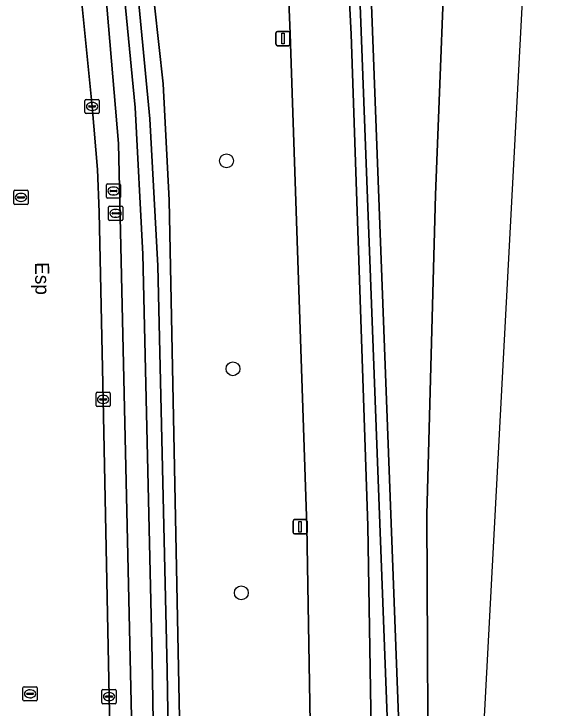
# Model space of a CAD drawing. Extents: x 161385 to 162589, y 388479 to 389756.
# Drawn here: x 162491.62 to 162530.48, y 389010.14 to 389059.08 of the extents above; entities that cross this region are included whole.
import ezdxf

# ---------------------------------------------------------------- set-up
doc = ezdxf.new("R2010")
doc.units = 0
for name, color, linetype in [('IMGEO_Berm_groen', 7, 'Continuous'), ('IMGEO_Boom', 7, 'Continuous'), ('IMGEO_Fietspad_gesloten', 7, 'Continuous'), ('IMGEO_Groenvoorziening', 7, 'Continuous'), ('IMGEO_Haag', 7, 'Continuous'), ('IMGEO_Kolk', 7, 'Continuous'), ('IMGEO_Lichtmast', 7, 'Continuous'), ('IMGEO_Oever', 7, 'Continuous'), ('IMGEO_Openbare_ruimte_label', 7, 'Continuous'), ('IMGEO_Rijbaan_lokaal_gesloten', 7, 'Continuous'), ('IMGEO_Rijbaan_regionaal_gesloten', 7, 'Continuous'), ('IMGEO_Rioolput', 7, 'Continuous'), ('IMGEO_Waterloop', 7, 'Continuous')]:
    doc.layers.add(name, color=color, linetype=linetype)

msp = doc.modelspace()

# ---------------------------------------------------------------- linework, layer by layer
at = {"layer": 'IMGEO_Berm_groen'}
for points in [[(162510.235, 389079.2), (162510.065, 389081.426), (162501.272, 389081.426), (162501.263, 389081.238), (162500.992, 389075.618), (162500.618, 389070.413), (162501.235, 389062.489), (162502.136, 389054.149), (162502.554, 389045.938), (162503.491, 389000), (162505.585, 388897.306), (162506.277, 388863.384)], [(162515.397, 389079.082), (162515.507, 389081.426), (162514.292, 389081.426), (162514.262, 389079.427), (162515.393, 389057.642), (162516.561, 389022.995), (162519.033, 388871.958), (162521.523, 388727.275)], [(162520.774, 388990.381), (162520.838, 389000), (162520.739, 389023.777), (162521.349, 389046.314), (162522.22, 389068.571), (162523.006, 389081.426), (162516.308, 389081.426), (162516.198, 389079.074), (162516.44, 389070.256), (162519.403, 388991.608), (162518.604, 388991.578), (162515.64, 389070.23)], [(162517.21, 388728.105), (162514.823, 388871.796), (162512.275, 389022.964), (162511.097, 389057.663), (162510.235, 389079.2)], [(162500, 389005.369), (162498.985, 389049.929), (162496.789, 389075.947)], [(162495.027, 389073.715), (162497.129, 389052.548), (162497.513, 389048.118), (162497.623, 389045.106), (162497.908, 389031.901), (162498.323, 389010.953), (162498.544, 389000)]]:
    msp.add_lwpolyline(points, dxfattribs=at)
at = {"layer": 'IMGEO_Boom'}
for centre in [(162506.603, 389048.718), (162507.06, 389034.063), (162507.648, 389018.266)]:
    msp.add_circle(centre, 0.489, dxfattribs=at)
at = {"layer": 'IMGEO_Fietspad_gesloten'}
msp.add_lwpolyline([(162519.033, 388871.958), (162516.561, 389022.995), (162515.393, 389057.642), (162514.262, 389079.427), (162514.292, 389081.426), (162514.386, 389087.66), (162514.743, 389099.436), (162509.811, 389099.872), (162509.798, 389099.728), (162509.789, 389099.382), (162509.527, 389088.495), (162510.065, 389081.426), (162510.235, 389079.2), (162511.097, 389057.663), (162512.275, 389022.964), (162514.823, 388871.796), (162517.21, 388728.105)], dxfattribs=at)
at = {"layer": 'IMGEO_Groenvoorziening'}
msp.add_lwpolyline([(162515.64, 389070.23), (162518.604, 388991.578), (162519.403, 388991.608), (162516.44, 389070.256), (162516.198, 389079.074), (162516.308, 389081.426), (162516.591, 389087.473), (162515.792, 389087.51), (162515.507, 389081.426), (162515.397, 389079.082)], dxfattribs=at)
at = {"layer": 'IMGEO_Haag'}
msp.add_lwpolyline([(162515.64, 389070.23), (162518.604, 388991.578), (162519.403, 388991.608), (162516.44, 389070.256), (162516.198, 389079.074), (162516.308, 389081.426), (162516.591, 389087.473), (162515.792, 389087.51), (162515.507, 389081.426), (162515.397, 389079.082)], dxfattribs=at)
at = {"layer": 'IMGEO_Kolk'}
for p, q in [((162496.629, 389052.123), (162496.629, 389052.975)), ((162496.704, 389053.049), (162497.556, 389053.049)), ((162497.117, 389052.829), (162497.142, 389052.829)), ((162497.63, 389052.975), (162497.63, 389052.123)), ((162496.888, 389052.543), (162496.888, 389052.555)), ((162497.326, 389052.506), (162496.928, 389052.506)), ((162496.931, 389052.592), (162497.329, 389052.592)), ((162497.372, 389052.555), (162497.372, 389052.543)), ((162497.556, 389052.049), (162496.704, 389052.049)), ((162497.14, 389052.269), (162497.115, 389052.269)), ((162497.408, 389031.475), (162497.408, 389032.327)), ((162497.483, 389032.401), (162498.335, 389032.401)), ((162498.409, 389032.327), (162498.409, 389031.475)), ((162497.667, 389031.895), (162497.667, 389031.907)), ((162498.105, 389031.858), (162497.707, 389031.858)), ((162497.71, 389031.944), (162498.108, 389031.944)), ((162497.896, 389032.181), (162497.921, 389032.181)), ((162498.151, 389031.907), (162498.151, 389031.895)), ((162498.335, 389031.401), (162497.483, 389031.401)), ((162497.919, 389031.621), (162497.894, 389031.621)), ((162497.823, 389010.527), (162497.823, 389011.379)), ((162497.898, 389011.453), (162498.75, 389011.453)), ((162498.311, 389011.233), (162498.336, 389011.233)), ((162498.824, 389011.379), (162498.824, 389010.527)), ((162498.082, 389010.947), (162498.082, 389010.959)), ((162498.52, 389010.91), (162498.122, 389010.91)), ((162498.125, 389010.996), (162498.523, 389010.996)), ((162498.566, 389010.959), (162498.566, 389010.947)), ((162498.75, 389010.453), (162497.898, 389010.453)), ((162498.334, 389010.673), (162498.309, 389010.673))]:
    msp.add_line(p, q, dxfattribs=at)
for points in [[(162496.629, 389052.123), (162496.629, 389052.975)], [(162496.704, 389053.049), (162497.556, 389053.049)], [(162497.63, 389052.975), (162497.63, 389052.123)], [(162497.556, 389052.049), (162496.704, 389052.049)], [(162497.408, 389031.475), (162497.408, 389032.327)], [(162497.483, 389032.401), (162498.335, 389032.401)], [(162498.409, 389032.327), (162498.409, 389031.475)], [(162498.335, 389031.401), (162497.483, 389031.401)], [(162497.823, 389010.527), (162497.823, 389011.379)], [(162497.898, 389011.453), (162498.75, 389011.453)], [(162498.824, 389011.379), (162498.824, 389010.527)], [(162498.75, 389010.453), (162497.898, 389010.453)]]:
    msp.add_lwpolyline(points, dxfattribs=at)
for centre, radius, start, end in [((162496.706, 389052.973), 0.0765, 91.552, 178.448), ((162496.706, 389052.973), 0.0765, 91.552, 178.448), ((162497.554, 389052.973), 0.0765, 1.552, 88.448), ((162497.554, 389052.973), 0.0765, 1.552, 88.448), ((162496.928, 389052.552), 0.0403, 85.8775, 175.7526), ((162496.925, 389052.542), 0.0366, 178.938, 274.7102), ((162497.329, 389052.549), 0.043, 264.8664, 352.4533), ((162497.333, 389052.554), 0.0386, 1.7309, 96.639), ((162496.706, 389052.125), 0.0765, 181.552, 268.448), ((162496.706, 389052.125), 0.0765, 181.552, 268.448), ((162497.554, 389052.125), 0.0765, 271.552, 358.448), ((162497.554, 389052.125), 0.0765, 271.552, 358.448), ((162497.485, 389032.325), 0.0765, 91.552, 178.448), ((162497.485, 389032.325), 0.0765, 91.552, 178.448), ((162498.333, 389032.325), 0.0765, 1.552, 88.448), ((162498.333, 389032.325), 0.0765, 1.552, 88.448), ((162497.707, 389031.904), 0.0403, 85.8775, 175.7526), ((162497.704, 389031.894), 0.0366, 178.938, 274.7102), ((162498.108, 389031.901), 0.043, 264.8664, 352.4533), ((162498.112, 389031.906), 0.0386, 1.7309, 96.639), ((162497.485, 389031.477), 0.0765, 181.552, 268.448), ((162497.485, 389031.477), 0.0765, 181.552, 268.448), ((162498.333, 389031.477), 0.0765, 271.552, 358.448), ((162498.333, 389031.477), 0.0765, 271.552, 358.448), ((162497.9, 389011.377), 0.0765, 91.552, 178.448), ((162497.9, 389011.377), 0.0765, 91.552, 178.448), ((162498.748, 389011.377), 0.0765, 1.552, 88.448), ((162498.748, 389011.377), 0.0765, 1.552, 88.448), ((162498.122, 389010.956), 0.0403, 85.8775, 175.7526), ((162498.119, 389010.946), 0.0366, 178.938, 274.7102), ((162498.523, 389010.953), 0.043, 264.8664, 352.4533), ((162498.527, 389010.958), 0.0386, 1.7309, 96.639), ((162497.9, 389010.529), 0.0765, 181.552, 268.448), ((162497.9, 389010.529), 0.0765, 181.552, 268.448), ((162498.748, 389010.529), 0.0765, 271.552, 358.448), ((162498.748, 389010.529), 0.0765, 271.552, 358.448)]:
    msp.add_arc(centre, radius, start, end, dxfattribs=at)
for centre, major_axis, ratio, start_param, end_param in [((162497.116, 389052.549), (-0.387, 0.002), 0.722429, 4.712389, 7.853982), ((162497.141, 389052.549), (-0.39, 0.002), 0.717154, 1.570796, 4.712389), ((162497.895, 389031.901), (-0.387, 0.002), 0.722429, 4.712389, 7.853982), ((162497.92, 389031.901), (-0.39, 0.002), 0.717154, 1.570796, 4.712389), ((162498.31, 389010.953), (-0.387, 0.002), 0.722429, 4.712389, 7.853982), ((162498.335, 389010.953), (-0.39, 0.002), 0.717154, 1.570796, 4.712389)]:
    msp.add_ellipse(centre, major_axis=major_axis, ratio=ratio, start_param=start_param, end_param=end_param, dxfattribs=at)
at = {"layer": 'IMGEO_Lichtmast'}
for p, q in [((162510.091, 389056.931), (162510.091, 389057.731)), ((162510.091, 389057.731), (162510.091, 389056.931)), ((162510.191, 389057.831), (162510.981, 389057.831)), ((162510.981, 389057.831), (162510.191, 389057.831)), ((162511.081, 389057.731), (162511.081, 389056.931)), ((162511.081, 389056.931), (162511.081, 389057.731)), ((162510.981, 389056.831), (162510.191, 389056.831)), ((162510.191, 389056.831), (162510.981, 389056.831)), ((162511.296, 389022.525), (162511.296, 389023.325)), ((162511.296, 389023.325), (162511.296, 389022.525)), ((162511.396, 389023.425), (162512.186, 389023.425)), ((162512.186, 389023.425), (162511.396, 389023.425)), ((162512.286, 389023.325), (162512.286, 389022.525)), ((162512.286, 389022.525), (162512.286, 389023.325)), ((162512.186, 389022.425), (162511.396, 389022.425)), ((162511.396, 389022.425), (162512.186, 389022.425))]:
    msp.add_line(p, q, dxfattribs=at)
for points in [[(162510.511, 389057.706), (162510.661, 389057.706), (162510.661, 389056.956), (162510.511, 389056.956), (162510.511, 389057.706)], [(162511.716, 389023.3), (162511.866, 389023.3), (162511.866, 389022.55), (162511.716, 389022.55), (162511.716, 389023.3)]]:
    msp.add_lwpolyline(points, dxfattribs=at)
for centre, start, end in [((162510.191, 389057.731), 90, 180), ((162510.191, 389057.731), 90, 180), ((162510.981, 389057.731), 0, 90), ((162510.981, 389057.731), 360, 90), ((162510.191, 389056.931), 180, 270), ((162510.191, 389056.931), 180, 270), ((162510.981, 389056.931), 270, 0), ((162510.981, 389056.931), 270, 0), ((162511.396, 389023.325), 90, 180), ((162511.396, 389023.325), 90, 180), ((162512.186, 389023.325), 0, 90), ((162512.186, 389023.325), 360, 90), ((162511.396, 389022.525), 180, 270), ((162511.396, 389022.525), 180, 270), ((162512.186, 389022.525), 270, 0), ((162512.186, 389022.525), 270, 0)]:
    msp.add_arc(centre, 0.1, start, end, dxfattribs=at)
at = {"layer": 'IMGEO_Oever'}
for points in [[(162499.467, 389089.001), (162499.159, 389089.128), (162495.15, 389090.013), (162494.837, 389089.198), (162494.779, 389089.009), (162494.49, 389088.06), (162496.788, 389086.825), (162496.788, 389081.502), (162496.789, 389075.947), (162498.985, 389049.929), (162500, 389005.369), (162500.109, 389000), (162502.143, 388899.896), (162502.197, 388897.243), (162503.945, 388811.232)], [(162504.505, 388860.971), (162503.038, 388926.396), (162502.659, 388946.624), (162502.127, 388965.964), (162501.881, 388981.345), (162501.365, 389013.623), (162500.705, 389042.133), (162500.155, 389052.486), (162498.345, 389071.465), (162498.581, 389076.587), (162498.739, 389086.449), (162498.772, 389086.623), (162498.826, 389086.782), (162498.892, 389086.879), (162499.066, 389086.995)], [(162499.712, 389086.909), (162499.807, 389086.78), (162499.841, 389086.613), (162499.834, 389086.44), (162499.637, 389075.77), (162499.401, 389070.648), (162501.211, 389051.669), (162501.761, 389041.317), (162502.421, 389012.807), (162502.937, 388980.529), (162503.183, 388965.148), (162503.715, 388945.808), (162504.093, 388925.58), (162505.561, 388860.155)], [(162502.554, 389045.938), (162502.136, 389054.149), (162501.235, 389062.489), (162500.618, 389070.413), (162500.992, 389075.618), (162501.263, 389081.238), (162501.272, 389081.426), (162501.334, 389084.856)], [(162506.277, 388863.384), (162505.585, 388897.306), (162503.491, 389000), (162502.554, 389045.938)]]:
    msp.add_lwpolyline(points, dxfattribs=at)
at = {"layer": 'IMGEO_Rijbaan_lokaal_gesloten'}
msp.add_lwpolyline([(162498.544, 389000), (162498.323, 389010.953), (162497.908, 389031.901), (162497.623, 389045.106), (162497.513, 389048.118), (162497.129, 389052.548), (162495.027, 389073.715)], dxfattribs=at)
at = {"layer": 'IMGEO_Rijbaan_regionaal_gesloten'}
msp.add_lwpolyline([(162530.479, 388820.962), (162524.33, 389000.689), (162529.323, 389094.968), (162523.871, 389095.21), (162523.594, 389091.03), (162523.006, 389081.426), (162522.22, 389068.571), (162521.349, 389046.314), (162520.739, 389023.777), (162520.838, 389000), (162520.774, 388990.381), (162522.364, 388884.975)], dxfattribs=at)
at = {"layer": 'IMGEO_Rioolput'}
for p, q in [((162498.139, 389046.167), (162498.139, 389047.019)), ((162498.214, 389047.093), (162499.066, 389047.093)), ((162499.14, 389047.019), (162499.14, 389046.167)), ((162491.615, 389045.714), (162491.615, 389046.566)), ((162491.69, 389046.64), (162492.542, 389046.64)), ((162492.616, 389046.566), (162492.616, 389045.714)), ((162498.398, 389046.587), (162498.398, 389046.599)), ((162498.836, 389046.55), (162498.438, 389046.55)), ((162498.441, 389046.636), (162498.839, 389046.636)), ((162498.627, 389046.873), (162498.652, 389046.873)), ((162498.882, 389046.599), (162498.882, 389046.587)), ((162491.874, 389046.134), (162491.874, 389046.146)), ((162492.312, 389046.097), (162491.914, 389046.097)), ((162491.917, 389046.183), (162492.315, 389046.183)), ((162492.103, 389046.42), (162492.128, 389046.42)), ((162492.358, 389046.146), (162492.358, 389046.134)), ((162499.066, 389046.093), (162498.214, 389046.093)), ((162498.65, 389046.313), (162498.625, 389046.313)), ((162492.542, 389045.64), (162491.69, 389045.64)), ((162492.126, 389045.86), (162492.101, 389045.86)), ((162498.361, 389045.516), (162499.213, 389045.516)), ((162498.286, 389044.59), (162498.286, 389045.442)), ((162498.545, 389045.01), (162498.545, 389045.022)), ((162498.983, 389044.973), (162498.585, 389044.973)), ((162498.588, 389045.059), (162498.986, 389045.059)), ((162498.774, 389045.296), (162498.799, 389045.296)), ((162499.029, 389045.022), (162499.029, 389045.01)), ((162499.287, 389045.442), (162499.287, 389044.59)), ((162499.213, 389044.516), (162498.361, 389044.516)), ((162498.797, 389044.736), (162498.772, 389044.736)), ((162492.257, 389010.722), (162492.257, 389011.574)), ((162492.332, 389011.648), (162493.184, 389011.648)), ((162492.745, 389011.428), (162492.77, 389011.428)), ((162493.258, 389011.574), (162493.258, 389010.722)), ((162492.516, 389011.142), (162492.516, 389011.154)), ((162492.954, 389011.105), (162492.556, 389011.105)), ((162492.559, 389011.191), (162492.957, 389011.191)), ((162492.768, 389010.868), (162492.743, 389010.868)), ((162493, 389011.154), (162493, 389011.142)), ((162493.184, 389010.648), (162492.332, 389010.648))]:
    msp.add_line(p, q, dxfattribs=at)
for points in [[(162498.139, 389046.167), (162498.139, 389047.019)], [(162498.214, 389047.093), (162499.066, 389047.093)], [(162499.14, 389047.019), (162499.14, 389046.167)], [(162491.615, 389045.714), (162491.615, 389046.566)], [(162491.69, 389046.64), (162492.542, 389046.64)], [(162492.616, 389046.566), (162492.616, 389045.714)], [(162499.066, 389046.093), (162498.214, 389046.093)], [(162492.542, 389045.64), (162491.69, 389045.64)], [(162498.361, 389045.516), (162499.213, 389045.516)], [(162498.286, 389044.59), (162498.286, 389045.442)], [(162499.287, 389045.442), (162499.287, 389044.59)], [(162499.213, 389044.516), (162498.361, 389044.516)], [(162492.257, 389010.722), (162492.257, 389011.574)], [(162492.332, 389011.648), (162493.184, 389011.648)], [(162493.258, 389011.574), (162493.258, 389010.722)], [(162493.184, 389010.648), (162492.332, 389010.648)]]:
    msp.add_lwpolyline(points, dxfattribs=at)
for centre, radius, start, end in [((162498.216, 389047.017), 0.0765, 91.552, 178.448), ((162498.216, 389047.017), 0.0765, 91.552, 178.448), ((162499.064, 389047.017), 0.0765, 1.552, 88.448), ((162499.064, 389047.017), 0.0765, 1.552, 88.448), ((162491.692, 389046.564), 0.0765, 91.552, 178.448), ((162491.692, 389046.564), 0.0765, 91.552, 178.448), ((162492.54, 389046.564), 0.0765, 1.552, 88.448), ((162492.54, 389046.564), 0.0765, 1.552, 88.448), ((162498.438, 389046.596), 0.0403, 85.8775, 175.7526), ((162498.435, 389046.586), 0.0366, 178.938, 274.7102), ((162498.839, 389046.593), 0.043, 264.8664, 352.4533), ((162498.843, 389046.598), 0.0386, 1.7309, 96.639), ((162491.914, 389046.143), 0.0403, 85.8775, 175.7526), ((162491.911, 389046.133), 0.0366, 178.938, 274.7102), ((162492.315, 389046.14), 0.043, 264.8664, 352.4533), ((162492.319, 389046.145), 0.0386, 1.7309, 96.639), ((162498.216, 389046.169), 0.0765, 181.552, 268.448), ((162498.216, 389046.169), 0.0765, 181.552, 268.448), ((162499.064, 389046.169), 0.0765, 271.552, 358.448), ((162499.064, 389046.169), 0.0765, 271.552, 358.448), ((162491.692, 389045.716), 0.0765, 181.552, 268.448), ((162491.692, 389045.716), 0.0765, 181.552, 268.448), ((162492.54, 389045.716), 0.0765, 271.552, 358.448), ((162492.54, 389045.716), 0.0765, 271.552, 358.448), ((162498.363, 389045.44), 0.0765, 91.552, 178.448), ((162498.363, 389045.44), 0.0765, 91.552, 178.448), ((162499.211, 389045.44), 0.0765, 1.552, 88.448), ((162499.211, 389045.44), 0.0765, 1.552, 88.448), ((162498.585, 389045.019), 0.0403, 85.8775, 175.7526), ((162498.582, 389045.009), 0.0366, 178.938, 274.7102), ((162498.986, 389045.016), 0.043, 264.8664, 352.4533), ((162498.99, 389045.021), 0.0386, 1.7309, 96.639), ((162498.363, 389044.592), 0.0765, 181.552, 268.448), ((162498.363, 389044.592), 0.0765, 181.552, 268.448), ((162499.211, 389044.592), 0.0765, 271.552, 358.448), ((162499.211, 389044.592), 0.0765, 271.552, 358.448), ((162492.334, 389011.572), 0.0765, 91.552, 178.448), ((162492.334, 389011.572), 0.0765, 91.552, 178.448), ((162493.182, 389011.572), 0.0765, 1.552, 88.448), ((162493.182, 389011.572), 0.0765, 1.552, 88.448), ((162492.334, 389010.724), 0.0765, 181.552, 268.448), ((162492.334, 389010.724), 0.0765, 181.552, 268.448), ((162492.556, 389011.151), 0.0403, 85.8775, 175.7526), ((162492.553, 389011.141), 0.0366, 178.938, 274.7102), ((162492.957, 389011.148), 0.043, 264.8664, 352.4533), ((162492.961, 389011.153), 0.0386, 1.7309, 96.639), ((162493.182, 389010.724), 0.0765, 271.552, 358.448), ((162493.182, 389010.724), 0.0765, 271.552, 358.448)]:
    msp.add_arc(centre, radius, start, end, dxfattribs=at)
for centre, major_axis, ratio, start_param, end_param in [((162498.626, 389046.593), (-0.387, 0.002), 0.722429, 4.712389, 7.853982), ((162498.651, 389046.593), (-0.39, 0.002), 0.717154, 1.570796, 4.712389), ((162492.102, 389046.14), (-0.387, 0.002), 0.722429, 4.712389, 7.853982), ((162492.127, 389046.14), (-0.39, 0.002), 0.717154, 1.570796, 4.712389), ((162498.773, 389045.016), (-0.387, 0.002), 0.722429, 4.712389, 7.853982), ((162498.798, 389045.016), (-0.39, 0.002), 0.717154, 1.570796, 4.712389), ((162492.744, 389011.148), (-0.387, 0.002), 0.722429, 4.712389, 7.853982), ((162492.769, 389011.148), (-0.39, 0.002), 0.717154, 1.570796, 4.712389)]:
    msp.add_ellipse(centre, major_axis=major_axis, ratio=ratio, start_param=start_param, end_param=end_param, dxfattribs=at)
at = {"layer": 'IMGEO_Waterloop'}
for points in [[(162499.066, 389086.995), (162498.892, 389086.879), (162498.826, 389086.782), (162498.772, 389086.623), (162498.739, 389086.449), (162498.581, 389076.587), (162498.345, 389071.465), (162500.155, 389052.486), (162500.705, 389042.133), (162501.365, 389013.623), (162501.881, 388981.345), (162502.127, 388965.964), (162502.659, 388946.624), (162503.038, 388926.396), (162504.505, 388860.971)], [(162505.561, 388860.155), (162504.093, 388925.58), (162503.715, 388945.808), (162503.183, 388965.148), (162502.937, 388980.529), (162502.421, 389012.807), (162501.761, 389041.317), (162501.211, 389051.669), (162499.401, 389070.648), (162499.637, 389075.77), (162499.834, 389086.44)]]:
    msp.add_lwpolyline(points, dxfattribs=at)

# ---------------------------------------------------------------- texts
at = {"layer": 'IMGEO_Openbare_ruimte_label'}
msp.add_text('Esp', height=1, rotation=271.1458, dxfattribs=at).set_placement((162493.097, 389041.564))

doc.saveas('drawing.dxf')
